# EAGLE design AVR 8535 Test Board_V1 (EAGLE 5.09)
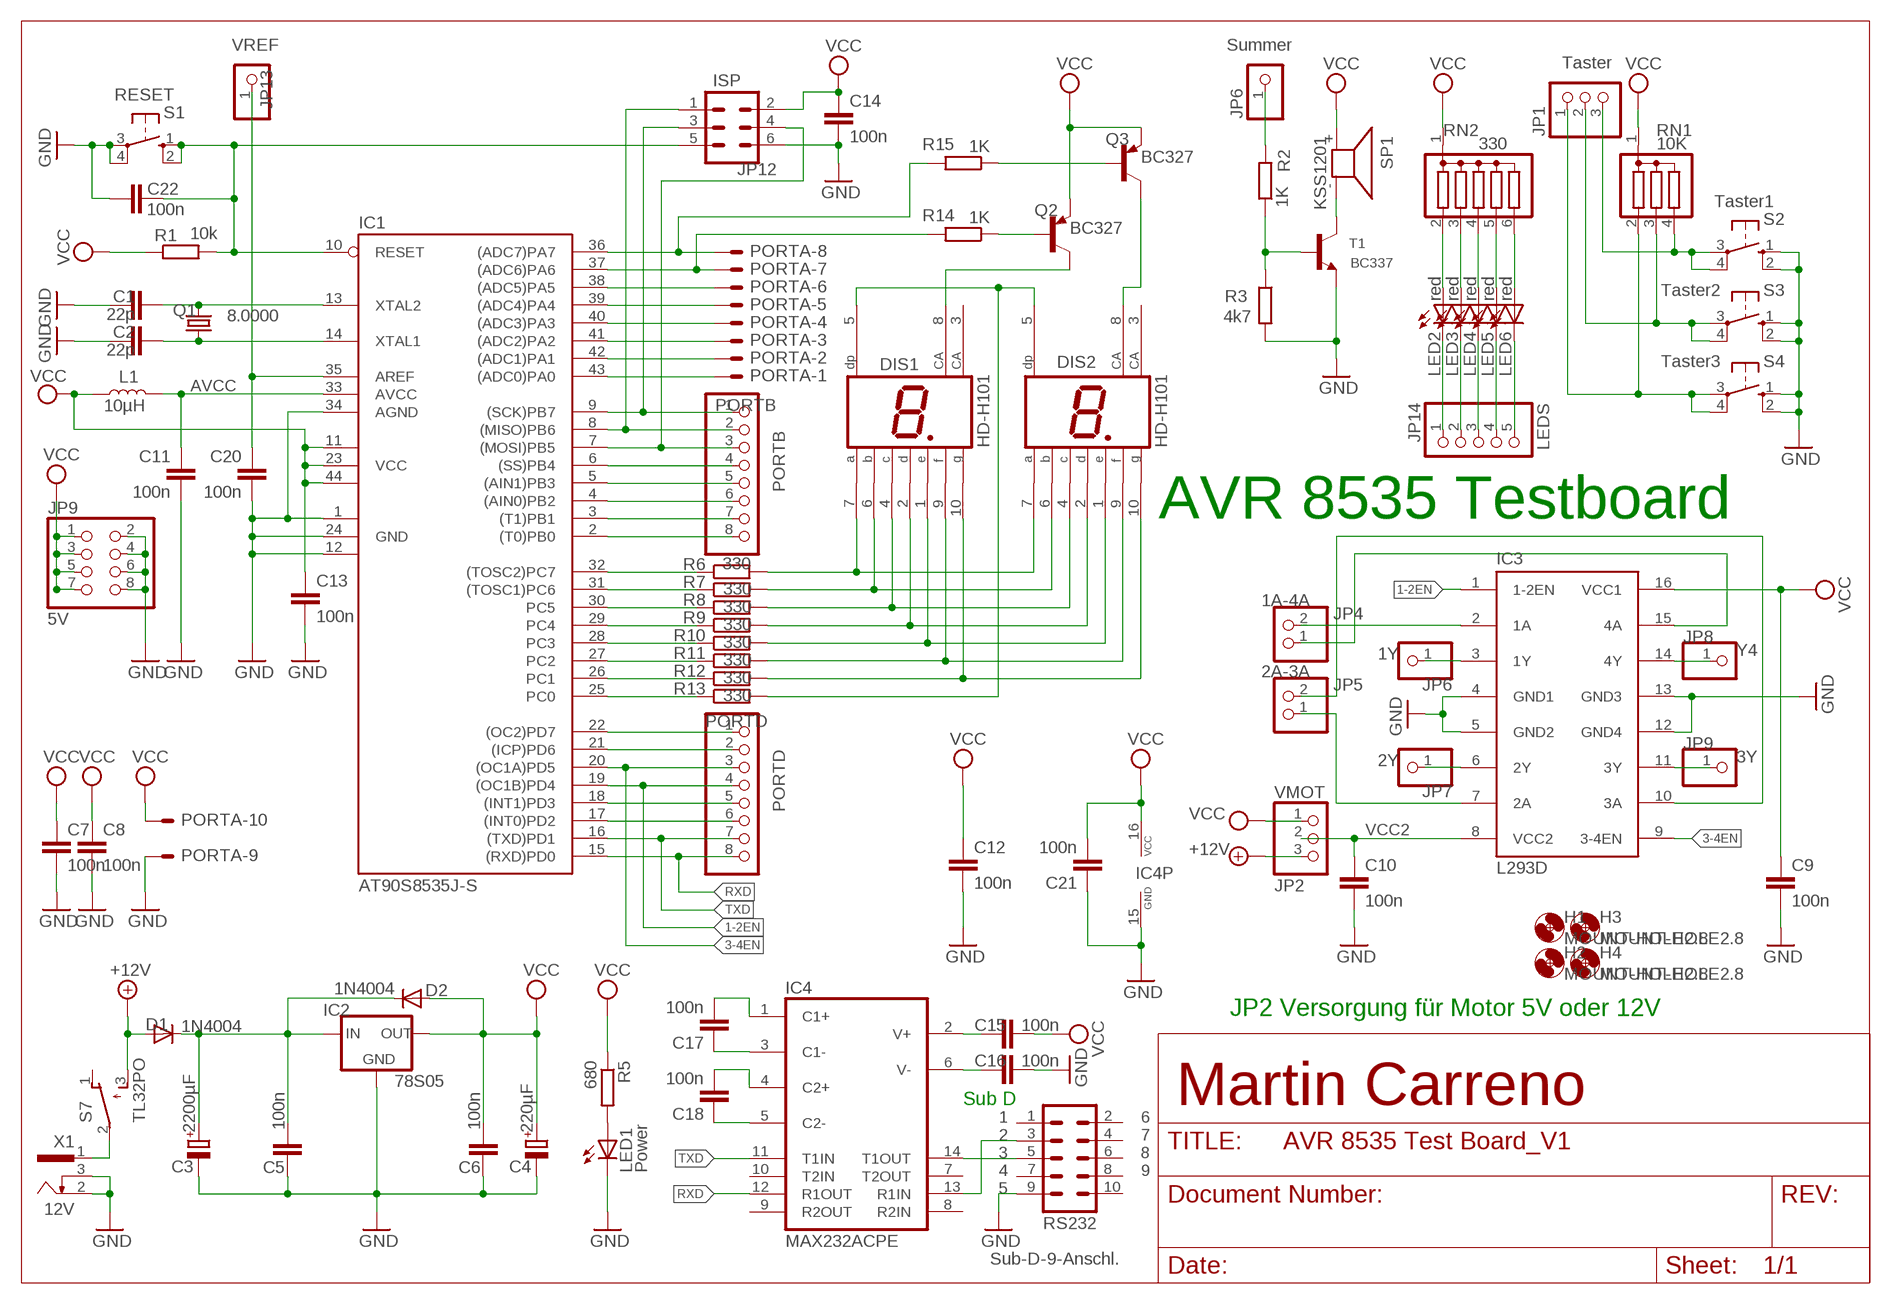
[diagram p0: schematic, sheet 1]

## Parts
1A-4A  JP4  PINHD-1X2  [1X02]
1Y  JP6  PINHD-1X1  [1X01]
2A-3A  JP5  PINHD-1X2  [1X02]
2Y  JP7  PINHD-1X1  [1X01]
3Y  JP9  PINHD-1X1  [1X01]
78S05  IC2  78XXS  [78XXS]
C1  22p  C-EU025-024X044  [C025-024X044]
C2  22p  C-EU025-024X044  [C025-024X044]
C3  2200µF  CPOL-EUE7.5-16  [E7,5-16]
C4  220µF  CPOL-EUE5-10.5  [E5-10,5]
C5  100n  C-EU050-024X044  [C050-024X044]
C6  100n  C-EU050-024X044  [C050-024X044]
C7  100n  C-EU025-024X044  [C025-024X044]
C8  100n  C-EU025-024X044  [C025-024X044]
C9  100n  C-EU050-024X044  [C050-024X044]
C10  100n  C-EU050-024X044  [C050-024X044]
C11  100n  C-EU025-024X044  [C025-024X044]
C12  100n  C-EU050-024X044  [C050-024X044]
C13  100n  C-EU025-024X044  [C025-024X044]
C14  100n  C-EU050-024X044  [C050-024X044]
C15  100n  C-EU050-024X044  [C050-024X044]
C16  100n  C-EU025-024X044  [C025-024X044]
C17  100n  C-EU050-024X044  [C050-024X044]
C18  100n  C-EU025-024X044  [C025-024X044]
C20  100n  C-EU025-024X044  [C025-024X044]
C21  100n  C-EU025-024X044  [C025-024X044]
C22  100n  C-EU025-024X044  [C025-024X044]
D1  1N4004  [DO41-10]
D2  1N4004  [DO41-10]
DIS1  HD-H101  [HDSP-M]
DIS2  HD-H101  [HDSP-M]
H1  MOUNT-HOLE2.8  [2,8]
H2  MOUNT-HOLE2.8  [2,8]
H3  MOUNT-HOLE2.8  [2,8]
H4  MOUNT-HOLE2.8  [2,8]
IC1  AT90S8535J-S  [S44]
IC3  L293D  [DIL16]
IC4  MAX232ACPE  [DIL16]
ISP  JP12  ML6  [ML6]
JP1  Taster  PINHD-1X3  [1X03]
JP6  Summer  PINHD-1X1  [1X01]
JP9  5V  PINHD-2X4  [2X04]
JP13  VREF  PINHD-1X1  [1X01]
JP14  LEDS  PINHD-1X5  [1X05]
L1  10µH  L-EU-0207/14  [0207/14]
LED1  Power  LED5MM  [LED5MM]
LED2  red  LED3MM  [LED3MM]
LED3  red  LED3MM  [LED3MM]
LED4  red  LED3MM  [LED3MM]
LED5  red  LED3MM  [LED3MM]
LED6  red  LED3MM  [LED3MM]
PORTA  ML10E  [ML10]
PORTB  PORTB  PINHD-1X8  [1X08]
PORTD  PORTD  PINHD-1X8  [1X08]
Q1  8.0000  CRYSTALHC49U-V  [HC49U-V]
Q2  BC327  [TO92-EBC]
Q3  BC327  [TO92-EBC]
R1  10k  R-EU_0204/5  [0204/5]
R2  1K  R-EU_0204/2V  [0204V]
R3  4k7  R-EU_0204/2V  [0204V]
R5  680  R-EU_0204/2V  [0204V]
R6  330  R-EU_0207/10  [0207/10]
R7  330  R-EU_0207/10  [0207/10]
R8  330  R-EU_0207/10  [0207/10]
R9  330  R-EU_0207/10  [0207/10]
R10  330  R-EU_0207/10  [0207/10]
R11  330  R-EU_0207/10  [0207/10]
R12  330  R-EU_0207/10  [0207/10]
R13  330  R-EU_0207/10  [0207/10]
R14  1K  R-EU_0207/15  [0207/15]
R15  1K  R-EU_0204/7  [0204/7]
RN1  10K  G03R  [SIL4]
RN2  330  G05R  [SIL6]
RS232  Sub-D-9-Anschl.  ML10  [ML10]
S1  RESET  10-XX  [B3F-10XX]
S2  Taster1  10-XX  [B3F-10XX]
S3  Taster2  10-XX  [B3F-10XX]
S4  Taster3  10-XX  [B3F-10XX]
S7  TL32PO  [TL3XPO]
SP1  KSS1201  [KSS1201]
T1  BC337  [TO92]
VMOT  JP2  PINHD-1X3  [1X03]
X1  12V  SCD-014A  [SCD-014-A]
Y4  JP8  PINHD-1X1  [1X01]

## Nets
1-2EN: IC1.19((OC1B)PD4) IC3.1(1-2EN) PORTD.4
1A: 1A-4A.2 IC3.2(1A)
1Y: 1Y.1 IC3.3(1Y)
2A: 2A-3A.1 IC3.7(2A)
2Y: 2Y.1 IC3.6(2Y)
3-4EN: IC1.20((OC1A)PD5) IC3.9(3-4EN) PORTD.3
3A: 2A-3A.2 IC3.10(3A)
3Y: 3Y.1 IC3.11(3Y)
4A: 1A-4A.1 IC3.15(4A)
4Y: IC3.14(4Y) Y4.1
+12V: D1.A S7.3(S) VMOT.3
AREF: C20.1 IC1.35(AREF) JP13.1
AVCC: C11.1 IC1.33(AVCC) L1.2
GND: 78S05.GND C1.1 C2.1 C3.- C4.- C5.2 C6.2 C7.2 C8.2 C9.2 C10.2 C11.2 C12.2 C13.2 C14.2 C16.2 C20.2 C21.1 C22.2 IC1.1(GND1) IC1.12(GND2) IC1.24(GND) IC1.34(AGND) IC3.4(GND1) IC3.5(GND2) IC3.12(GND4) IC3.13(GND3) IC4.15(GND) ISP.6 JP9.2 JP9.4 JP9.6 JP9.8 LED1.K(C) PORTA.9 R3.2 RS232.9 S1.3(P) S1.4(P1) S2.1(S) S2.2(S1) S3.1(S) S3.2(S1) S4.1(S) S4.2(S1) T1.3(E) X1.2 X1.3
MISO: IC1.8((MISO)PB6) ISP.1 PORTB.2
MOSI: IC1.7((MOSI)PB5) ISP.4 PORTB.3
N$3: 78S05.IN C3.+ C5.1 D1.C D2.C
N$10: JP6.1 R2.2
N$22: LED1.A R5.2
N$30: LED6.A RN2.6
N$31: JP1.3 RN1.4 S2.3(P) S2.4(P1)
N$32: C15.1 IC4.2(V+)
N$34: JP14.5 LED6.K(C)
N$37: JP1.2 RN1.3 S3.3(P) S3.4(P1)
N$38: JP1.1 RN1.2 S4.3(P) S4.4(P1)
N$41: DIS1.7(A) DIS2.7(A) R6.2
N$42: DIS1.6(B) DIS2.6(B) R7.2
N$43: DIS1.4(C) DIS2.4(C) R8.2
N$44: DIS1.2(D) DIS2.2(D) R9.2
N$45: DIS1.1(E) DIS2.1(E) R10.2
N$46: DIS1.9(F) DIS2.9(F) R11.2
N$47: DIS1.10(G) DIS2.10(G) R12.2
N$48: DIS1.8(CA) Q2.C
N$49: DIS2.8(CA) Q3.C
N$50: DIS1.5(DP) DIS2.5(DP) R13.2
N$51: Q3.B R15.1
N$52: Q2.B R14.1
N$55: SP1.- T1.1(C)
N$60: S7.2(P) X1.1
N$61: R2.1 R3.1 T1.2(B)
N$66: JP14.1 LED2.K(C)
N$67: JP14.2 LED3.K(C)
N$68: JP14.3 LED4.K(C)
N$73: JP14.4 LED5.K(C)
N$76: C16.1 IC4.6(V-)
N$77: LED5.A RN2.5
N$78: LED4.A RN2.4
N$79: LED3.A RN2.3
N$80: LED2.A RN2.2
N$81: C17.1 IC4.3(C1-)
N$82: C17.2 IC4.1(C1+)
N$83: C18.1 IC4.5(C2-)
N$84: C18.2 IC4.4(C2+)
N$85: IC4.14(T1OUT) RS232.5
N$86: IC4.13(R1IN) RS232.3
PA0: IC1.43((ADC0)PA0) PORTA.1
PA1: IC1.42((ADC1)PA1) PORTA.2
PA2: IC1.41((ADC2)PA2) PORTA.3
PA3: IC1.40((ADC3)PA3) PORTA.4
PA4: IC1.39((ADC4)PA4) PORTA.5
PA5: IC1.38((ADC5)PA5) PORTA.6
PA6: IC1.37((ADC6)PA6) PORTA.7 R14.2
PA7: IC1.36((ADC7)PA7) PORTA.8 R15.2
PB0: IC1.2((T0)PB0) PORTB.8
PB1: IC1.3((T1)PB1) PORTB.7
PB2: IC1.4((AIN0)PB2) PORTB.6
PB3: IC1.5((AIN1)PB3) PORTB.5
PB4: IC1.6((SS)PB4) PORTB.4
PC0: IC1.25(PC0) R13.1
PC1: IC1.26(PC1) R12.1
PC2: IC1.27(PC2) R11.1
PC3: IC1.28(PC3) R10.1
PC4: IC1.29(PC4) R9.1
PC5: IC1.30(PC5) R8.1
PC6: IC1.31((TOSC1)PC6) R7.1
PC7: IC1.32((TOSC2)PC7) R6.1
PD2: IC1.17((INT0)PD2) PORTD.6
PD3: IC1.18((INT1)PD3) PORTD.5
PD6: IC1.21((ICP)PD6) PORTD.2
PD7: IC1.22((OC2)PD7) PORTD.1
RESET: C22.1 IC1.10(RESET) ISP.5 R1.2 S1.1(S) S1.2(S1)
RXD: IC1.15((RXD)PD0) IC4.12(R1OUT) PORTD.8
SCK: IC1.9((SCK)PB7) ISP.3 PORTB.1
TXD: IC1.16((TXD)PD1) IC4.11(T1IN) PORTD.7
VCC: 78S05.OUT C4.+ C6.1 C7.1 C8.1 C9.1 C12.1 C13.1 C14.1 C15.2 C21.2 D2.A IC1.11(VCC1) IC1.23(VCC) IC1.44(VCC2) IC3.16(VCC1) IC4.16(VCC) ISP.2 JP9.1 JP9.3 JP9.5 JP9.7 L1.1 PORTA.10 Q2.E Q3.E R1.1 R5.1 RN1.1 RN2.1 SP1.+ VMOT.1
VCC2: C10.1 IC3.8(VCC2) VMOT.2
XTAL1: C2.2 IC1.14(XTAL1) Q1.1
XTAL2: C1.2 IC1.13(XTAL2) Q1.2
Unconnected: DIS1.3(CA) DIS2.3(CA) IC4.7(T2OUT) IC4.8(R2IN) IC4.9(R2OUT) IC4.10(T2IN) RS232.1 RS232.2 RS232.4 RS232.6 RS232.7 RS232.8 RS232.10 S7.1(O)

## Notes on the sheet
- AVR 8535 Testboard
- JP2 Versorgung für Motor 5V oder 12V
- Sub D | Martin Carreno
- 1 | 6
- 2 | 7
- 3 | 8
- 4 | 9
- 5

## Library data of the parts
1A-4A 2A-3A = pinhead:PINHD-1X2: PIN HEADER
1Y 2Y 3Y JP6 JP13 Y4 = pinhead:PINHD-1X1: PIN HEADER
78S05 = v-reg:78XXS: VOLTAGE REGULATOR
C1 C2 C7-C18 C20-C22 = rcl:C-EU: CAPACITOR, European symbol
C3 C4 = rcl:CPOL-EU: POLARIZED CAPACITOR, European symbol
C5 C6 = resistor:C-EU: CAPACITOR, European symbol
D1 D2 = diode:1N4004: DIODE
DIS1 DIS2 = display-hp:HD-H101: LED DISPLAY 1-character 7 segment, decimal point right; OC_FARNELL: unknown; OC_NEWARK: unknown
H1-H4 = holes:MOUNT-HOLE: MOUNTING HOLE with drill center marker
IC1 = atmel:AT90*8535: MICROCONTROLLER 8 Kbytes FLASH 512 bytes SRAM 512 bytes EEPROM UART 8-channel 10 bit ADC; OC_FARNELL: unknown; OC_NEWARK: unknown
IC3 = st-microelectronics:L293D: PUSH-PULL 4 CHANNEL DRIVER; MPN: L293D; OC_FARNELL: 9589619; OC_NEWARK: 56P8249
IC4 = max-232:MAX232A*: RS-232 Transceiver with smaller Capacitors
ISP = con-harting-ml:ML6: HARTING; OC_FARNELL: unknown; OC_NEWARK: unknown
JP1 VMOT = pinhead:PINHD-1X3: PIN HEADER
JP9 = pinhead:PINHD-2X4: PIN HEADER
JP14 = pinhead:PINHD-1X5: PIN HEADER
L1 = L-EU-207-14:L-EU-0207/14: Inductor Length 14 mm
LED1-LED6 = led:LED: LED
PORTA = con-harting-ml:ML10?E: HARTING; OC_FARNELL: unknown; OC_NEWARK: unknown
PORTB PORTD = pinhead:PINHD-1X8: PIN HEADER
Q1 = crystal:CRYSTAL: CRYSTAL; OC_FARNELL: 1666969; OC_NEWARK: unknown
Q2 Q3 = transistor-pnp:BC327*: PNP Transistror
R1-R3 R5-R15 = rcl:R-EU_: RESISTOR, European symbol
RN1 = resistor-sil:G03R: SIL RESISTOR; OC_FARNELL: unknown; OC_NEWARK: unknown
RN2 = resistor-sil:G05R: SIL RESISTOR; OC_FARNELL: unknown; OC_NEWARK: unknown
RS232 = con-harting-ml:ML10: HARTING; OC_FARNELL: unknown; OC_NEWARK: unknown
S1-S4 = switch-omron:10-XX: OMRON SWITCH; MPN: B3F-1000; OC_FARNELL: 176432; OC_NEWARK: 36M3542
S7 = switch:TL32PO: TINY SWITCH ON - MOM Source: http://www2.produktinfo.conrad.com/datenblaetter/700000-724999/705152-da-01-de-Subminiaturschalter_TL_36YO.pdf
SP1 = buzzer:KSS1201: SPEAKER; OC_FARNELL: unknown; OC_NEWARK: unknown
T1 = transistor-JP:BC337: Transistor NPN TO-92 50v, 800mA, 625mW
X1 = con-shiua-chyuan:SCD-014A: Power Jack 2.5mm; OC_FARNELL: unknown; OC_NEWARK: unknown

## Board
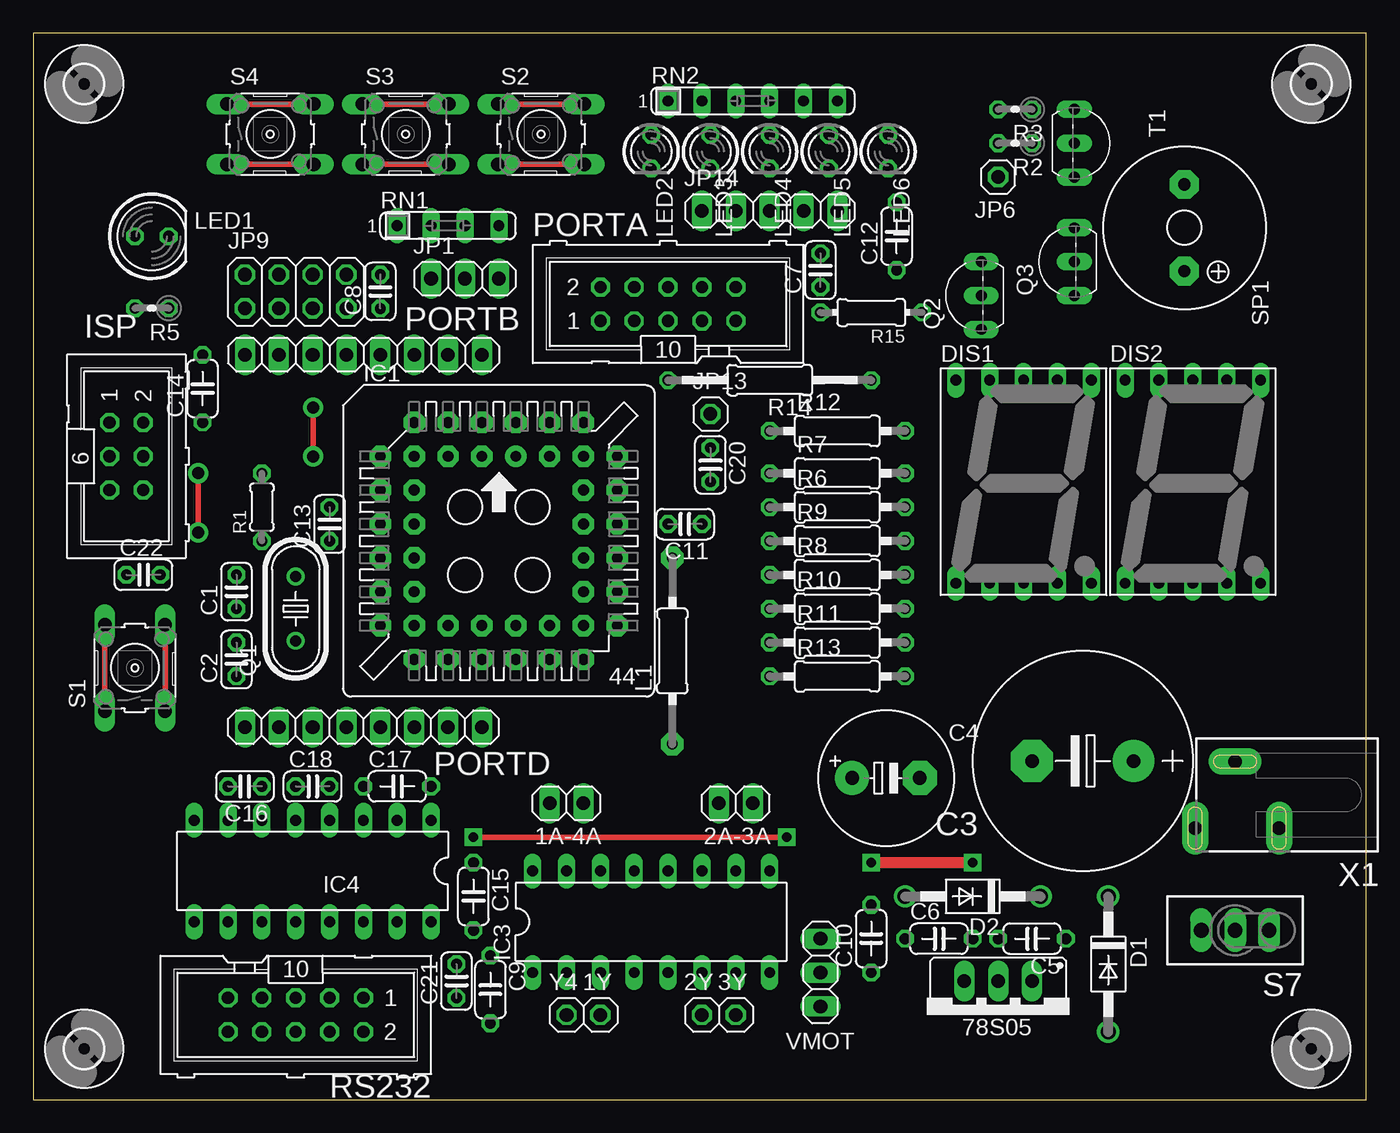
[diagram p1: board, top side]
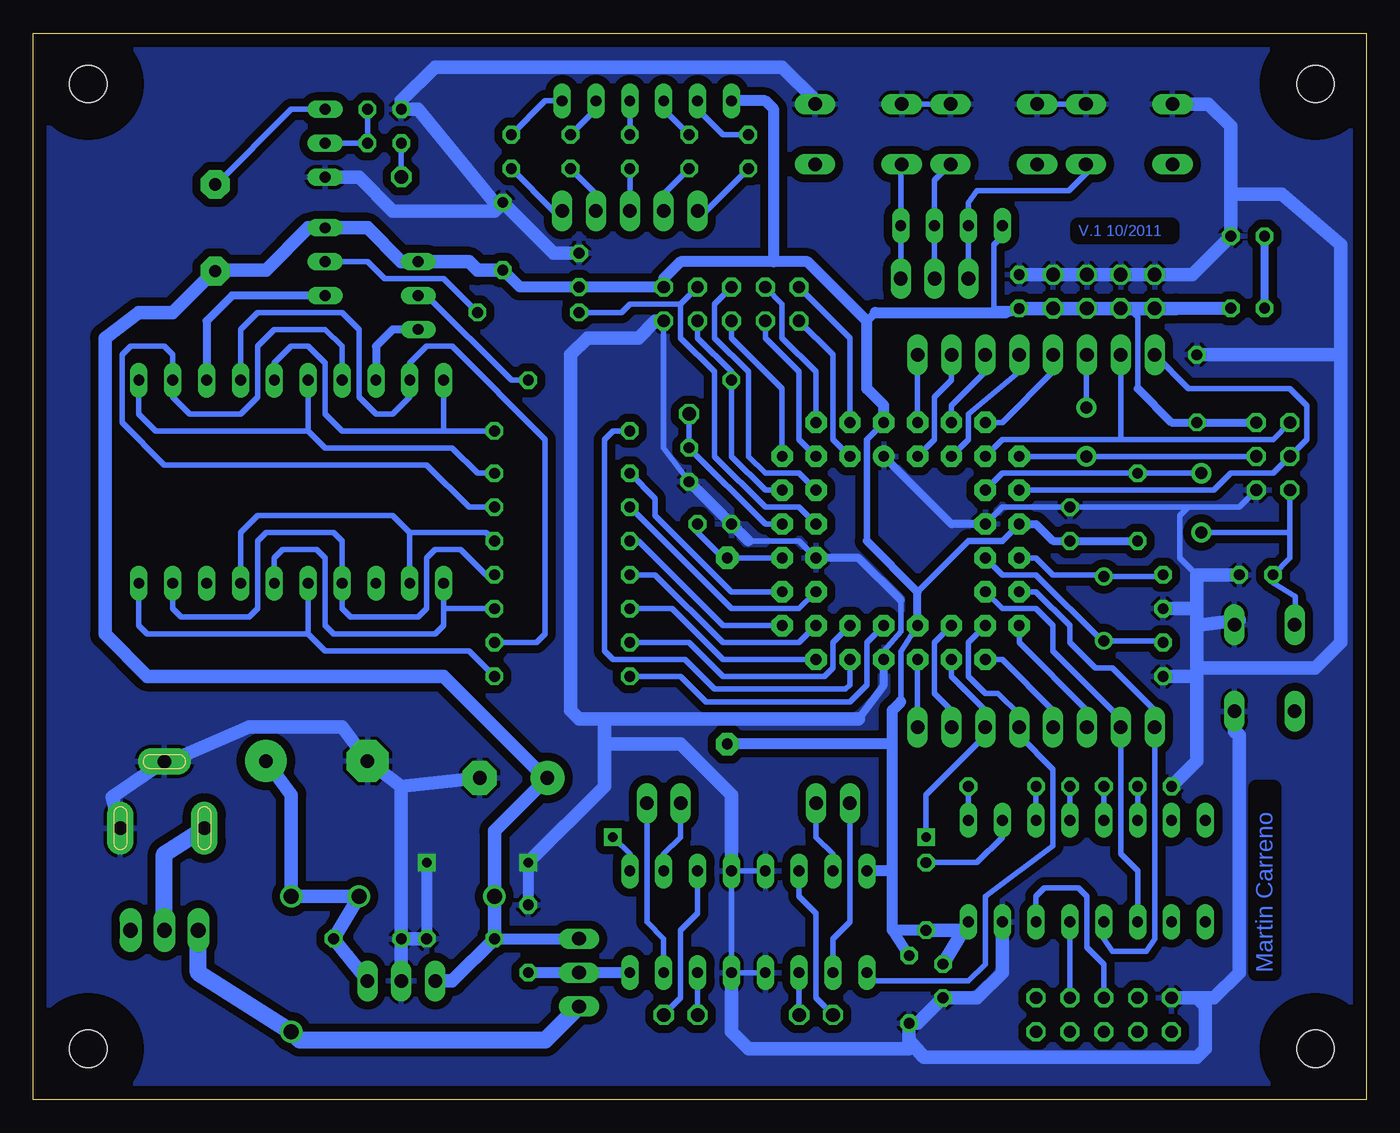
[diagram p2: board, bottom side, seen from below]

Size 100 x 80 mm. Coordinates in mm from the lower left corner, seen from the top.
Outline: 0,0 100,0 100,80 0,80 0,0
Copper layers (1*16): Top 0.035mm / dielectric 1.5mm / Bottom 0.035mm
Design rules "default *": minimum track width 10mil, minimum drill 24mil, track to track 8mil, track to pad 8mil, pad to pad 8mil, via to via 8mil, smd to smd 8mil, copper to edge 40mil, drill to drill 8mil, minimum pad ring 10mil, minimum via ring 12mil, stop-mask expansion 4mil, vias tented up to drill 0mil, thermal gap 10mil

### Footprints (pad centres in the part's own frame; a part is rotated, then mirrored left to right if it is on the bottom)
1X02 = drill 1.016 long: 1 -1.27,0; 2 1.27,0
1X01 = drill 1.016 octagon: 1 0,0
78XXS = drill 1.016 long: GND 0,-2.54; IN -2.54,-2.54; OUT 2.54,-2.54
C025-024X044 = drill 0.813 octagon: 1 -1.27,0; 2 1.27,0
E7,5-16 = drill 1.016 pad 3.15 round: + -3.81,0 | drill 1.016 pad 3.15 octagon: - 3.81,0
E5-10,5 = drill 1.016 pad 2.54 round: + -2.54,0 | drill 1.016 pad 2.54 octagon: - 2.54,0
C050-024X044 = drill 0.813 octagon: 1 -2.54,0; 2 2.54,0
DO41-10 = drill 1.118 round: A 5.08,0; C -5.08,0
HDSP-M = drill 0.813 long: 1 -5.08,-7.62; 2 -2.54,-7.62; 3 0,-7.62; 4 2.54,-7.62; 5 5.08,-7.62; 6 5.08,7.62; 7 2.54,7.62; 8 0,7.62; 9 -2.54,7.62; 10 -5.08,7.62
2,8 = hole 2.8: 0,0
S44 = drill 0.813 pad 1.6 round: 1 1.27,6.35 | drill 0.813 pad 1.6 octagon: 2 -1.27,8.89; 3 -1.27,6.35; 4 -3.81,8.89; 5 -3.81,6.35; 6 -6.35,8.89; 7 -8.89,6.35; 8 -6.35,6.35; 9 -8.89,3.81; 10 -6.35,3.81; 11 -8.89,1.27; 12 -6.35,1.27; 13 -8.89,-1.27; 14 -6.35,-1.27; 15 -8.89,-3.81; 16 -6.35,-3.81; 17 -8.89,-6.35; 18 -6.35,-8.89; 19 -6.35,-6.35; 20 -3.81,-8.89; 21 -3.81,-6.35; 22 -1.27,-8.89; 23 -1.27,-6.35; 24 1.27,-8.89; 25 1.27,-6.35; 26 3.81,-8.89; 27 3.81,-6.35; 28 6.35,-8.89; 29 8.89,-6.35; 30 6.35,-6.35; 31 8.89,-3.81; 32 6.35,-3.81; 33 8.89,-1.27; 34 6.35,-1.27; 35 8.89,1.27; 36 6.35,1.27; 37 8.89,3.81; 38 6.35,3.81; 39 8.89,6.35; 40 6.35,8.89; 41 6.35,6.35; 42 3.81,8.89; 43 3.81,6.35; 44 1.27,8.89
DIL16 = drill 0.813 long: 1 -8.89,-3.81; 2 -6.35,-3.81; 3 -3.81,-3.81; 4 -1.27,-3.81; 5 1.27,-3.81; 6 3.81,-3.81; 7 6.35,-3.81; 8 8.89,-3.81; 9 8.89,3.81; 10 6.35,3.81; 11 3.81,3.81; 12 1.27,3.81; 13 -1.27,3.81; 14 -3.81,3.81; 15 -6.35,3.81; 16 -8.89,3.81
ML6 = drill 0.914 octagon: 1 -2.54,-1.27; 2 -2.54,1.27; 3 0,-1.27; 4 0,1.27; 5 2.54,-1.27; 6 2.54,1.27
1X03 = drill 1.016 long: 1 -2.54,0; 2 0,0; 3 2.54,0
2X04 = drill 1.016 octagon: 1 -3.81,-1.27; 2 -3.81,1.27; 3 -1.27,-1.27; 4 -1.27,1.27; 5 1.27,-1.27; 6 1.27,1.27; 7 3.81,-1.27; 8 3.81,1.27
1X05 = drill 1.016 long: 1 -5.08,0; 2 -2.54,0; 3 0,0; 4 2.54,0; 5 5.08,0
0207/14 = drill 0.813 pad 1.676 octagon: 1 -6.985,0; 2 6.985,0
LED5MM = drill 0.813 octagon: A -1.27,0; K 1.27,0
LED3MM = drill 0.813 octagon: A -1.27,0; K 1.27,0
ML10 = drill 0.914 octagon: 1 -5.08,-1.27; 2 -5.08,1.27; 3 -2.54,-1.27; 4 -2.54,1.27; 5 0,-1.27; 6 0,1.27; 7 2.54,-1.27; 8 2.54,1.27; 9 5.08,-1.27; 10 5.08,1.27
1X08 = drill 1.016 long: 1 -8.89,0; 2 -6.35,0; 3 -3.81,0; 4 -1.27,0; 5 1.27,0; 6 3.81,0; 7 6.35,0; 8 8.89,0
HC49U-V = drill 0.813 round: 1 -2.413,0; 2 2.413,0
TO92-EBC = drill 0.813 long: B 0,-1.27; C -2.54,-1.27; E 2.54,-1.27
0204/5 = drill 0.813 octagon: 1 -2.54,0; 2 2.54,0
0204V = drill 0.813 octagon: 1 -1.27,0; 2 1.27,0
0207/10 = drill 0.813 octagon: 1 -5.08,0; 2 5.08,0
0207/15 = drill 0.813 octagon: 1 -7.62,0; 2 7.62,0
0204/7 = drill 0.813 octagon: 1 -3.81,0; 2 3.81,0
SIL4 = drill 0.813 long: 1 -3.81,0; 2 -1.27,0; 3 1.27,0; 4 3.81,0
SIL6 = drill 0.813 long: 1 -6.35,0; 2 -3.81,0; 3 -1.27,0; 4 1.27,0; 5 3.81,0; 6 6.35,0
B3F-10XX = drill 1.016 long: 1 -3.251,2.261; 2 3.251,2.261; 3 -3.251,-2.261; 4 3.251,-2.261
TL3XPO = drill 1.1 pad 1.422 long: 1 -2.54,0; 2 0,0; 3 2.54,0
KSS1201 = drill 0.914 pad 2.159 octagon: + 3.251,0; - -3.251,0
TO92 = drill 0.813 long: 1 -2.54,0; 2 0,0; 3 2.54,0
SCD-014-A = drill 1 pad 2 long: 1 -2.5,13.8; 2 -2.5,7.5; 3 2.5,10.8

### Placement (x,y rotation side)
1A-4A  40.01,22.23 180 top
1Y  42.55,6.35 0 top
2A-3A  52.7,22.23 180 top
2Y  50.16,6.35 0 top
3Y  52.7,6.35 0 top
78S05  72.39,6.35 180 top
C1  15.24,38.1 90 top
C2  15.24,33.02 90 top
C3  78.74,25.4 180 top
C4  63.97,24.13 0 top
C5  74.93,12.06 180 top
C6  67.94,12.06 0 top
C7  59.05,62.23 90 top
C8  26.04,60.62 90 top
C9  34.29,8.26 270 top
C10  62.87,12.06 90 top
C11  48.9,43.18 180 top
C12  64.77,64.77 90 top
C13  22.23,43.18 90 top
C14  12.7,53.34 90 top
C15  33.02,15.24 270 top
C16  15.88,23.5 180 top
C17  27.3,23.5 0 top
C18  20.95,23.5 0 top
C20  50.8,47.62 270 top
C21  31.75,8.89 90 top
C22  8.26,39.37 0 top
D1  80.64,10.16 270 top
D2  70.48,15.24 180 top
DIS1  74.3,46.35 0 top
DIS2  87,46.35 0 top
H1  3.81,76.2 0 top
H2  3.81,3.81 0 top
H3  95.89,76.2 0 top
H4  95.89,3.81 0 top
IC1  34.92,41.91 0 top
IC3  46.35,13.34 0 top
IC4  20.95,17.14 180 top
ISP  6.99,48.26 270 top
JP1  32.38,61.59 0 top
JP6  72.39,69.22 180 top
JP9  19.68,60.62 0 top
JP13  50.8,51.44 0 top
JP14  55.24,66.67 0 top
L1  47.94,33.66 90 top
LED1  8.89,64.77 0 top
LED2  46.35,71.12 270 top
LED3  50.8,71.12 270 top
LED4  55.24,71.12 270 top
LED5  59.69,71.12 270 top
LED6  64.14,71.12 270 top
PORTA  47.62,59.69 0 top
PORTB  24.77,55.88 0 top
PORTD  24.77,27.94 180 top
Q1  19.68,36.83 90 top
Q2  69.85,60.33 90 top
Q3  76.83,62.87 90 top
R1  17.14,44.45 90 top
R2  73.66,71.75 180 top
R3  73.66,74.3 180 top
R5  8.89,59.37 180 top
R6  60.33,44.45 0 top
R7  60.33,46.99 0 top
R8  60.33,39.37 0 top
R9  60.33,41.91 0 top
R10  60.33,36.83 0 top
R11  60.33,34.29 0 top
R12  60.33,50.16 0 top
R13  60.33,31.75 0 top
R14  55.24,53.98 180 top
R15  62.87,59.05 180 top
RN1  31.11,65.56 0 top
RN2  53.98,74.93 0 top
RS232  19.68,6.35 180 top
S1  7.62,32.38 90 top
S2  38.1,72.44 0 top
S3  27.94,72.44 0 top
S4  17.78,72.44 0 top
S7  90.17,12.7 180 top
SP1  86.36,65.41 270 top
T1  78.11,71.75 270 top
VMOT  59.05,9.53 270 top
X1  100.97,22.86 90 top
Y4  40.01,6.35 0 top

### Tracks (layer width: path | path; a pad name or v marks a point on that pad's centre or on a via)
1-2EN
  Bottom 0.406: IC1.19 29.84,34.29 29.84,31.75 28.57,30.48 27.62,30.48 26.04,28.89 PORTD.4 26.04,27.3 23.5,24.77 23.5,19.05 28.57,15.24 28.57,10.16 29.84,8.89 36.83,8.89 IC3.1
1A
  Bottom 0.406: IC3.2 40.01,12.06 38.73,13.34 1A-4A.2
1Y
  Bottom 0.406: 1Y.1 IC3.3
2A
  Bottom 0.406: IC3.7 52.7,12.06 53.98,13.34 2A-3A.1
2Y
  Bottom 0.406: 2Y.1 IC3.6
3-4EN  (via drill 0.7)
  Top 0.406: v33.02,19.68 v56.52,19.68
  Bottom 0.406: IC1.20 31.11,31.75 28.57,29.21 PORTD.3 28.57,27.3 33.02,22.86 v33.02,19.68 | IC3.9 55.24,18.41 v56.52,19.68
3A
  Bottom 0.406: 2A-3A.2 51.44,19.68 52.7,18.41 IC3.10
3Y
  Bottom 0.406: IC3.11 50.16,13.97 51.44,12.7 51.44,7.62 3Y.1
4A
  Bottom 0.406: 1A-4A.1 41.27,19.68 40.01,18.41 IC3.15
4Y
  Bottom 0.406: IC3.14 42.55,15.24 41.27,13.97 41.27,7.62 Y4.1
+12V
  Bottom 1.27: S7.3 87.63,9.53 D1.A 80.01,4.45 61.59,4.45 VMOT.3
AREF
  Bottom 0.406: IC1.35 45.09,43.18 C20.1 JP13.1
AVCC
  Bottom 0.406: C11.1 50.16,42.55 48.26,40.64 L1.2 IC1.33
GND  (via drill 0.7)
  Top 0.406: S4.1 S4.2 | S3.1 S3.2 | S2.1 S2.2 | S1.3 S1.4
  Top 0.813: v62.87,17.78 v70.48,17.78
  Bottom 0.406: IC1.12 27.3,44.45 C13.2 13.34,44.45 | 13.34,44.45 9.53,44.45 ISP.6 | 13.34,44.45 13.97,43.81 13.97,40.64 12.7,39.37 | IC1.34 42.55,41.91 46.35,41.91 | PORTA.9 52.7,48.9 C20.2 | 34.92,37.47 34.92,35.13 36.2,33.66 IC1.24 | S4.2 S3.1 | S3.2 S2.1 | S1.4 9.53,35.99 | 12.7,32.38 12.7,31.75 | C2.1 15.51,31.75 | IC3.13 IC3.12 IC3.5 IC3.4
  Bottom 0.61: IC1.12 31.11,43.18 IC1.1 | IC1.24 36.2,31.11 38.1,28.57 | IC1.34 38.1,40.64 34.92,37.47
  Bottom 0.813: C20.2 C11.2 46.35,41.91 | v70.48,17.78 C6.2 | v62.87,17.78 C10.2
  Bottom 1.016: 12.7,36.83 C1.1 | C16.2 12.7,25.4 12.7,31.75 C2.1 | X1.2 94.1,22.7 X1.3 88.31,26 83.82,27.94 76.83,27.94 C3.- 72.39,23.5 | IC4.15 27.3,9.53 29.21,7.62 C21.1 33.66,5.71 C9.2 34.29,4.45 | 72.39,23.5 C4.- | C5.2 78S05.GND | C6.2 C5.2 | C5.2 72.39,23.5 | C22.2 12.7,39.37 12.7,36.83 | 57.15,28.57 38.1,28.57 | 57.15,26.67 57.15,23.5 v62.87,17.78 | 9.53,35.99 12.7,35.56 | 12.7,35.56 12.7,32.38 3.81,32.38 1.91,34.29 1.91,55.88 | 12.7,35.56 12.7,36.83 | 57.15,26.67 57.15,28.57 | 57.15,26.67 51.44,26.67 47.62,22.86 IC3.12 | 34.29,4.45 34.29,3.81 46.35,3.81 47.62,5.08 IC3.5 | 34.29,4.45 33.17,3.17 12.7,3.17 12.06,3.81 12.06,6.99 12.7,7.62 RS232.9 11.43,7.62 9.53,9.53 9.53,27.3 9.88,27.66 S1.3 | S4.1 11.83,74.7 10.16,73.03 10.16,67.94 | 10.16,67.94 LED1.K 13.04,61.9 JP9.2 JP9.4 JP9.6 JP9.8 C8.2 | 10.16,67.94 6.35,67.94 1.91,64.14 1.91,55.88 | 1.91,55.88 C14.2 | C7.2 60.96,63.5 C12.2 | C12.2 65.41,67.31 71.12,74.3 R3.2 72.39,74.93 69.85,77.47 43.81,77.47 41.27,74.93 41.35,74.85 S2.2 | T1.3 75.56,69.22 73.03,66.67 65.41,66.67 C12.2 | 53.34,58.42 54.61,57.15 58.42,57.15 59.69,55.88 59.69,29.21 59.05,28.57 57.15,28.57
  pour Bottom (isolate 0.61): 0,0 0,80.64 100.42,80.74 99.79,0
MISO
  Bottom 0.406: 18.41,49.53 6.99,49.53 ISP.1 | 18.41,49.53 27.3,49.53 IC1.8 | 18.41,49.53 PORTB.2
MOSI  (via drill 0.9)
  Top 0.406: v21,48.26 v21,51.93
  Bottom 0.406: ISP.4 v21,48.26 IC1.7 | v21,51.93 21,55.84 PORTB.3
N$3
  Bottom 1.016: 78S05.IN C5.1 D2.C D1.C 80.64,22.86 C3.+
N$10
  Bottom 0.406: JP6.1 R2.2
N$22
  Bottom 0.61: R5.2 LED1.A
N$30
  Bottom 0.406: RN2.6 61.59,74.93 LED6.A
N$31
  Top 0.406: S2.3 S2.4
  Bottom 0.406: S2.3 34.92,69.62 RN1.4 JP1.3
N$32
  Bottom 0.406: IC4.2 27.3,19.68 29.21,17.78 C15.1
N$34
  Bottom 0.406: JP14.5 60.96,66.67 LED6.K
N$37
  Top 0.406: S3.4 S3.3
  Bottom 0.406: S3.4 32.38,68.98 RN1.3 JP1.2
N$38
  Top 0.406: S4.3 S4.4
  Bottom 0.406: S4.4 20.95,69.54 22.29,68.2 29.21,68.2 29.84,67.31 RN1.2 JP1.1
N$41
  Bottom 0.406: DIS1.7 76.83,56.52 78.11,57.78 81.92,57.78 83.19,56.52 83.19,52.7 84.45,51.44 88.27,51.44 89.53,52.7 DIS2.7 89.53,55.88 90.17,56.52 92.71,56.52 93.34,55.88 93.34,50.8 90.17,47.62 70.48,47.62 67.31,44.45 R6.2
N$42
  Bottom 0.406: DIS2.6 92.08,51.44 90.81,50.16 79.38,50.16 | 79.38,50.16 DIS1.6 | 79.38,50.16 78.11,48.9 68.58,48.9 66.67,46.99 R7.2
N$43
  Bottom 0.406: DIS2.4 89.53,36.83 88.9,36.2 83.82,36.2 83.19,36.83 83.19,41.91 82.55,42.55 77.47,42.55 76.83,41.91 DIS1.4 76.83,36.83 76.2,36.2 71.12,36.2 70.48,36.83 70.48,40.64 69.85,41.27 67.94,41.27 66.04,39.37 R8.2
N$44
  Bottom 0.406: DIS2.2 84.45,42.55 83.19,43.81 73.03,43.81 71.75,42.55 | R9.2 66.04,42.55 71.75,42.55 | 71.75,42.55 DIS1.2
N$45
  Bottom 0.406: DIS2.1 81.92,40.64 81.28,41.27 78.74,41.27 78.11,40.64 78.11,35.56 77.47,34.92 69.85,34.92 69.22,35.56 69.22,36.83 | 69.22,36.83 DIS1.1 | R10.2 69.22,36.83
N$46
  Bottom 0.406: DIS2.9 84.45,57.78 83.19,59.05 76.83,59.05 75.56,57.78 75.56,52.7 74.3,51.44 73.03,51.44 71.75,52.7 DIS1.9 71.75,55.24 70.48,56.52 68.58,56.52 61.59,49.53 61.59,34.92 62.23,34.29 R11.2
N$47
  Bottom 0.406: 69.22,50.16 DIS1.10 | 69.22,50.16 76.83,50.16 78.11,51.44 78.11,55.24 79.38,56.52 80.64,56.52 81.92,55.24 DIS2.10 | R12.2 69.22,50.16
N$48
  Bottom 0.61: DIS1.8 74.3,56.52 73.03,57.78 Q2.C
N$49
  Bottom 0.61: Q3.C 85.09,60.33 87,58.42 DIS2.8
N$50
  Bottom 0.406: 79.38,34.92 DIS1.5 | 79.38,34.92 91.44,34.92 92.08,35.56 DIS2.5 | 79.38,34.92 78.11,33.66 67.31,33.66 R13.2
N$51
  Bottom 0.406: Q3.B 74.93,62.87 73.66,61.59 69.22,61.59 R15.1
N$52
  Bottom 0.406: R14.1 64.14,53.98 70.48,60.33 Q2.B
N$55
  Bottom 0.406: SP1.- 86.36,68.58 80.64,74.3 T1.1
N$60
  Bottom 0.813: S7.2 90.17,12.91
  Bottom 1.27: X1.1 90.17,18.41 90.17,12.91
N$61
  Bottom 0.406: T1.2 R2.1 R3.1
N$66
  Bottom 0.406: LED2.K 49.53,66.67 JP14.1
N$67
  Bottom 0.406: JP14.2 52.7,67.94 LED3.K
N$68
  Bottom 0.406: JP14.3 LED4.K
N$73
  Bottom 0.406: LED5.K 57.78,67.94 JP14.4
N$76
  Bottom 0.406: IC4.6 C16.1
N$77
  Bottom 0.406: RN2.5 57.78,74.3 LED5.A
N$78
  Bottom 0.406: LED4.A RN2.4
N$79
  Bottom 0.406: RN2.3 52.7,74.3 LED3.A
N$80
  Bottom 0.406: LED2.A 48.26,72.39 50.16,74.3 RN2.2
N$81
  Bottom 0.406: IC4.3 C17.1
N$82
  Bottom 0.406: IC4.1 C17.2
N$83
  Bottom 0.406: IC4.5 C18.1
N$84
  Bottom 0.406: IC4.4 C18.2
N$85
  Bottom 0.406: IC4.14 24.77,15.24 24.13,15.88 21.59,15.88 20.95,15.24 20.95,11.43 19.68,10.16 RS232.5
N$86
  Bottom 0.406: RS232.3 IC4.13
PA0
  Bottom 0.406: IC1.43 40.01,49.53 40.01,55.88 PORTA.1
PA1
  Bottom 0.406: PORTA.2 38.73,57.15 IC1.42
PA2
  Bottom 0.406: PORTA.3 45.09,57.15 42.55,54.61 42.55,49.53 IC1.41
PA3
  Bottom 0.406: PORTA.4 43.81,59.69 43.81,57.15 41.27,54.61 IC1.40
PA4
  Bottom 0.406: PORTA.5 47.62,57.15 43.81,53.34 IC1.39
PA5
  Bottom 0.406: IC1.38 42.55,46.99 45.09,46.99 46.35,48.26 46.35,54.61 48.9,57.15 48.9,59.69 PORTA.6
PA6
  Bottom 0.406: PORTA.7 50.16,57.15 47.62,54.61 R14.2 47.62,48.26 45.09,45.72 IC1.37
PA7
  Bottom 0.406: IC1.36 42.55,44.45 45.09,44.45 48.9,48.26 48.9,54.61 51.44,57.15 51.44,59.69 | 51.44,59.69 PORTA.8 | R15.2 55.88,59.05 55.24,59.69 51.44,59.69
PB0
  Bottom 0.406: IC1.2 PORTB.8
PB1
  Bottom 0.406: IC1.3 32.38,49.53 32.38,52.7 31.11,53.98 PORTB.7
PB2
  Bottom 0.406: PORTB.6 28.57,54.61 31.11,52.07 IC1.4
PB3
  Bottom 0.406: IC1.5 29.84,49.53 29.84,51.44 26.04,54.61 PORTB.5
PB4
  Bottom 0.406: PORTB.4 23.5,54.61 27.3,50.8 IC1.6
PC0
  Bottom 0.406: IC1.25 37.47,34.29 37.47,31.11 38.73,29.84 49.53,29.84 51.44,31.75 R13.1
PC1
  Bottom 0.406: IC1.26 38.73,31.11 39.05,30.8 48.9,30.8 51.12,33.02 56.52,33.02 57.15,33.66 57.15,49.53 56.52,50.16 R12.1
PC2
  Bottom 0.406: IC1.27 40.01,34.29 40.01,32.38 40.64,31.75 48.26,31.75 50.8,34.29 R11.1
PC3
  Bottom 0.406: R10.1 52.07,36.83 48.26,33.02 IC1.28
PC4
  Bottom 0.406: R9.1 54.61,41.91 48.26,35.56 IC1.29
PC5
  Bottom 0.406: IC1.30 42.55,34.29 48.26,34.29 53.34,39.37 R8.1
PC6
  Bottom 0.406: IC1.31 47.62,38.1 53.34,43.81 53.34,45.09 R7.1
PC7
  Bottom 0.406: IC1.32 42.55,36.83 47.62,36.83 R6.1
PD2
  Bottom 0.406: IC1.17 26.04,34.29 20.95,29.21 PORTD.6
PD3
  Bottom 0.406: IC1.18 27.3,33.02 23.5,29.21 PORTD.5
PD6
  Bottom 0.406: IC1.21 32.38,34.29 32.38,30.48 31.11,29.21 PORTD.2
PD7
  Bottom 0.406: PORTD.1 IC1.22
RESET  (via drill 0.9)
  Top 0.406: v12.37,42.55 v12.37,46.99 | S1.1 S1.2
  Bottom 0.406: IC1.10 27.3,46.99 R1.2 v12.37,46.99 | 5.71,42.55 ISP.5 | 5.71,42.55 v12.37,42.55 | 5.71,42.55 5.71,40.64 C22.1 6.99,38.77 5.32,37.74 5.32,37.26 S1.2
RXD
  Bottom 0.406: IC1.15 24.77,38.1 22.23,35.56 22.23,34.29 20.32,32.38 19.05,32.38 15.88,29.21 PORTD.8 15.88,12.06 16.51,11.11 19.05,11.11 19.68,12.06 IC4.12
SCK
  Bottom 0.406: PORTB.1 13.34,53.34 5.71,53.34 4.45,52.07 4.45,49.53 ISP.3 6.99,46.99 10.16,46.99 11.43,45.72 IC1.9
TXD
  Bottom 0.406: IC1.16 27.3,36.83 24.77,36.83 23.5,35.56 23.5,33.66 18.41,28.57 PORTD.7 18.41,18.41 17.14,17.14 IC4.11
VCC
  Bottom 0.406: 26.97,59.05 26.67,59.05 | 17.14,53.34 17.14,58.72 17.78,59.35 | IC1.23 34.92,33.63 34.92,29.84 | C8.1 27.94,59.35 27.94,64.14 27.3,64.77 RN1.1
  Bottom 0.5: 33.66,38.1 29.84,41.91 27.3,41.91 IC1.11 | IC1.44 37.47,49.53 37.47,46.99 37.47,41.91
  Bottom 0.61: 26.67,59.05 C8.1 | JP9.3 17.78,59.35 | 37.47,58.42 36.83,59.05 | ISP.2 C14.1 14.61,50.8 17.14,53.34 | 52.7,61.59 PORTA.10 | IC1.23 33.66,38.1 37.47,41.91 | IC1.11 24.77,43.18 23.5,41.91 C13.1 R1.1
  Bottom 0.813: RN2.1 45.09,74.93 44.45,74.3 44.45,62.87 | 36.83,59.05 26.97,59.05 | PORTA.10 C7.1 63.5,60.96 C12.1 | 44.45,62.87 41.91,62.87 37.47,58.42 37.47,53.34 36.2,52.07 IC1.44 | 44.45,62.87 51.44,62.87 52.7,61.59 | IC4.16 30.48,12.7 | 34.92,29.84 35.56,29.21 35.56,26.67 | 35.56,17.14 IC3.16 | 35.56,17.14 35.56,26.67 | 35.56,12.7 C9.1 | C15.2 35.56,12.7 | 35.56,12.7 35.56,17.14 | C6.1 VMOT.1 | 35.56,26.67 L1.1
  Bottom 1.016: C21.2 IC4.16 | 78S05.OUT 68.58,8.89 C6.1 D2.A 65.41,20.16 C4.+ 62.06,24.6 69.22,31.75 91.44,31.75 94.61,34.92 94.61,57.15 92.08,59.05 89.53,59.05 86.36,62.23 | JP9.3 JP9.5 JP9.7 C8.1 | 17.78,59.35 JP9.1 14.27,59.35 R5.1 | 30.48,12.7 C15.2 | C12.1 66.67,62.23 67.31,62.87 Q2.E 72.39,62.87 74.93,65.41 Q3.E 79.38,65.41 82.55,62.23 86.36,62.23 | 86.36,62.23 SP1.+
VCC2
  Bottom 0.813: IC3.8 VMOT.2 C10.1
XTAL1
  Bottom 0.305: Q1.1 19.81,34.42
  Bottom 0.406: 19.81,34.42 24.77,39.37 27.3,39.37 IC1.14 | Q1.1 15.63,34.42 C2.2
XTAL2
  Bottom 0.406: C1.2 15.63,39.24 Q1.2 19.81,39.37 23.5,39.37 24.77,40.64 IC1.13

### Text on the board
Bottom: V.1 10/2011 | Martin Carreno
